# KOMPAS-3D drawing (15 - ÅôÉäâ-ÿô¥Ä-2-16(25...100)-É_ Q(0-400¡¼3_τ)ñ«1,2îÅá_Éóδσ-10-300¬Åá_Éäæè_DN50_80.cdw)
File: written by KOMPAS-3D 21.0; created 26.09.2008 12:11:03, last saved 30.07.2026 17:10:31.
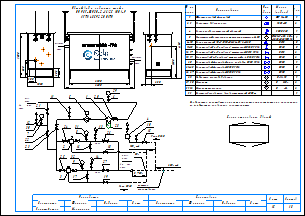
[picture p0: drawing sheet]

Sheets 1-2: A3, landscape

Document properties: Наименование: Макро:21; Автор: RaskoAdmin; Форматы листов документа: 2xA3; Полное имя файла: \\ur38nt01\Departments\КТО\КБ ПУРДГ\Заявки\Прайс-лист на типовые шкафы ГРПШ\ПУРДГ_стандарт_30_04_2026\ПУРДГ с РДСК\ПУРДГ-ШУЭО-2-16(25...100)-Р_ Q(0-400нм3_ч)до1,2МПа_Рвых-10-300кПа_РДСК_DN50_80.cdw

Title block, sheet 1: Наименование: Пункт учета газа / ПУГ-Ш-400-Р / ЛГТИ.485922.001ТУ; designation: ЛГТИ.03.4411141; sheet number: 1; Количество листов документа: 2; organisation: ООО "ЭЛЬСТЕР Газэлектроника"; Форматы листов документа: A3; stored path: C:\Рабочие документы\Компас\ПУГ\Схема.cdw; Разработал: Устинов; Проверил: Кошкин; Утвердил: Кошкин
Title block, sheet 2: sheet number: 2; stored path: D:\Рабочие документы\Заявки\ПУРДГ\ПУРДГ-ШУЭО-2-100-Р 4411220.cdw; designation, second copy: ЛГТИ.03.4411141-

Views: Вид 1, Вид 2
Referenced files: wcvoit.frw
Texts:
  Normal
  № на
  схеме
  Усл.
  обозн.
  Марка
  (модель)
  Кол.
  Фильтр газовый фланцевый
  ФГ 16-50
  Регулятор давления газа
  РДСК-50
  Клапан предохранительный сбросной
  КПС DN20
  Измерительный комплекс с ротационным счетчиком Ду50
  СГ-ЭК-Р-(0,2...2,0)-
  Кран кнопочный VE-РАСКО-НЗ-1,6-G1/2-М20
  DN15
  Кран шаровой "под приварку" штуцерный DN20 PN16
  DN20
  Кран шаровой "под приварку" штуцерный DN15 PN16
  Кран шаровой "под приварку" штуцерный п/п DN20 PN16
  Кран шаровой фланцевый с мех. приводом DN50 PN16
  Кран шаровой фланцевый DN50 PN16
  Кран шаровой фланцевый DN80 PN16
  DN50
  DN80
  Индикатор перепада давления
  Манометр
  Манометр-напоромер
  Электрообогреватель взрывозащищенный 400Вт
  Delta 15
  0...     МПа
  0...     кПа
  Общий вид и габариты шкафа
  ПУРДГ-ШУЭО-2-16(25...100)-Р
  Выход газа
  Вход газа
  logo-rasko-ge.png
  DN 1
  местное
  сопротивление
  Римп DN20
  Выход
  газа
  Р=     кПа
  Вход
  Р=       МПа
  PDI
  Схема открывания дверей
  Предприятие изготовитель может заменять комплектующие на аналогичные,
  не ухудшающие заявленных характеристик.
  Должность
  Конструктор
  Фамилия
  Подпись
  Дата
  Согласовано
  Максимкин
  Лист
  Листов
  POLYLINE_STYLE_0.18_RGB_0_0_0
  POLYLINE_STYLE_0.50_RGB_0_0_0
  POLYLINE_STYLE_0.34_RGB_0_0_0
  PHANTOM_RGB_0_0_0_SC_1_THICK_0.18
  K5LT_THIN_RGB_0_0_0_THICK_0.18
  K5LT32769_RGB_0_0_0_THICK_0.18
  K5LT12_RGB_0_0_0_SC_1_THICK_0.18
  K5LT_DASHED_RGB_0_0_0_SC_1_THICK_0.18
  ACISOTGL_RGB_0_0_0_SC_0.8_THICK_0.25
  CONTINUOUS_RGB_0_127_31_THICK_0.3
  CONTINUOUS_RGB_0_0_255_THICK_0.35
  CONTINUOUS_RGB_255_0_0_THICK_0.35
  POLYLINE_STYLE_0.25_RGB_0_0_0
  CONTINUOUS_RGB_0_0_0_THICK_0.5
  POLYLINE_STYLE_0.35_RGB_0_0_255
  CONTINUOUS_RGB_0_0_0_THICK_0.4
  CONTINUOUS_RGB_0_0_0_THICK_0.35
  НЕВИДИМАЯ_RGB_0_0_0_SC_0.3_THICK_0.25
  СONTINUOUS_RGB_0_0_0_THICK_0.25
  ОСЕВАЯ2_RGB_248_153_30_SC_0.3_THICK_0.25
  Без оформления
Dimensions and other numbers on the sheet: 1; 2, 3; 2; 4; 5; 6-10; 11-15; 16, 17; 18, 19; 20; 21-25; 26, 27; 28; 29, 30; 31, 32; 33; 1500; 250; 300; 1050; 550; 305; 2300; 4130; 2000; 2600; 5,,,7DN 1; 7; 30; 12; 21; 22; 23; 11; 6; 29; 24; 31; 8; 16; 13; 26; 18; 10; 15; 25; 32; 9; 3; 17; 14; 27; 19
